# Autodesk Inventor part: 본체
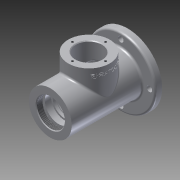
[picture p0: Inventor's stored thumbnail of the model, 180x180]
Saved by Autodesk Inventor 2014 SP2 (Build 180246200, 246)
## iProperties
Created: 2016-08
Part Number: 본체
Material: 알루미늄 6061
Document SubType Name: Modeling
Designer: 달림반
Density: 2.71 g/cm^3
Appearance: 알루미늄 - 평지
Author: 달림반
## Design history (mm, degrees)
sketch "스케치1"
  geometry: L1 (-56, 31)-(59, 31); L2 (59, 31)-(59, 21); L3 (59, 21)-(46.991, 16.711); L4 (45, 13.886)-(45, 12.904); L5 (44.3, 12.5)-(38, 12.5); L6 (37.7, 12.2)-(37.7, 10); L7 (37.7, 10)-(35, 10); L8 (35, 10)-(35, 13.5); L9 (32, 16.5)-(30, 16.5); L10 (30, 16.5)-(30, 17.2); L11 (29.7, 17.5)-(-35, 17.5); L12 (-35, 17.5)-(-35, 20); L13 (-35, 20)-(-44, 20); L14 (-44, 20)-(-44, 24); L15 (-44, 24)-(-47, 24); L16 (-47, 24)-(-47, 20); L17 (-47, 20)-(-56, 20); L18 (-56, 20)-(-56, 31); L19 (0, 0)-(59, 0); L20 (-31.75, 17.5)-(-31.75, 18.5); L21 (-31.75, 18.5)-(-30, 18.5); L22 (-30, 18.5)-(-30, 17.5); L23 (44.3, 12.5)-(45, 12.904); A1 r 0.3 centre (38, 12.2) between (38, 12.5) and (37.7, 12.2); A2 r 0.3 centre (29.7, 17.2) between (30, 17.2) and (29.7, 17.5); A3 r 3 centre (48, 13.886) between (46.991, 16.711) and (45, 13.886); A4 r 3 centre (32, 13.5) between (35, 13.5) and (32, 16.5); 3 further points
  constraints: 47 end point, 12 parallel, 8 point on circle, 8 point on line, 8 tangent, 7 perpendicular, 4 centre point, 1 collinear, 1 equal radius, 1 horizontal, 1 vertical alignment
  dimensions: "d0" = 115 distance between parallel lines of L2 L18; "d1" = 56 distance from line of L19.start L18; "d2" = 62 diameter of L1 L19; "d3" = 42 diameter of L2.end L19; "d4" = 32 diameter of point (45, 16) L19; "d5" = 25 diameter of L5 L19; "d6" = 20 diameter of L7 L19; "d7" = 2.7 distance of L6.end L7.end; "d9" = 33 diameter of L9 L19; "d10" = 40 diameter of L17 L19; "d12" = 48 diameter of L15 L19; "d13" = 12 distance between parallel lines of L14 L18; "d14" = 3 distance of L14.end L15.end; "d15" = 21 distance between parallel lines of L18 L12; "d16" = 40 diameter of L13 L19; "d17" = 35 diameter of L11 L19; "d18" = 1.75 distance of L20.end L21.end; "d19" = 26 distance between parallel lines of L18 L22; "d20" = 37 diameter of L21 L19; "d22" = 14 distance from line of L2 point (45, 16); "d23" = 60 distance between parallel lines of L10 L22; "d24" = 5 distance between parallel lines of L10 L8 (derived); "d25" = 24 distance between parallel lines of L2 L8 (derived); "d26" = 86 distance between parallel lines of L18 L10 (derived); "d27" = 0.3 radius of A1; "d28" = 0.3 radius of A2; "d29" = 30 deg angle of L23 L5; "d30" = 0.7 horizontal distance of L5.start L4.end; "d31" = 7.3 distance between parallel lines of L4 L6; "d33" = 3 radius of A3
revolve "회전1" sketch "스케치1" stored, may be unused: angle "d32" = 90 deg
node "작업 평면1"
sketch "스케치2"
  geometry: C1 r 31 at (0, 0) reference; C2 r 50 at (0, 0); 1 further point
  constraints: 1 centre point, 1 coincident
  dimensions: "d35" = 100 diameter of C2
extrude "돌출1" join sketch "스케치2" distance "d36" = 10; taper "d37" = 0 deg
node "작업 평면2"
sketch "스케치3"
  geometry: C1 r 30 at (0, 0); 1 further point
  constraints: 1 centre point, 1 coincident
  dimensions: "d39" = 60 diameter of C1
extrude "돌출2" join sketch "스케치3" stored distance "d41" = 10; taper "d42" = 0 deg
sketch "스케치4"
  geometry: L1 (-19, 0)-(19, 0); L2 (19, 0)-(19, -26); L3 (19, -26)-(-19, -26); L4 (-19, -26)-(-19, 0); 2 further points
  constraints: 8 end point, 2 parallel, 1 coincident, 1 horizontal, 1 horizontal alignment, 1 midpoint, 1 perpendicular
  dimensions: "d43" = 52 diameter of L3 L1; "d45" = 38 distance between parallel lines of L2 L4
revolve "회전2" sketch "스케치4" stored, may be unused: angle "d44" = 90 deg
sketch "스케치5"
  geometry: C1 r 30 at (0, 0) reference; C2 r 19 at (0, 0)
  constraints: 1 centre point, 1 coincident
  dimensions: "d46" = 38 diameter of C2
extrude "돌출3" cut sketch "스케치5" stored distance "d47" = 10; taper "d48" = 0 deg
hole "구멍1" diameter "d54" = 40.376; stored, may be unused: countersink angle "d58" = 90 deg, drill point angle "d60" = 0 deg; dims "d55" = 6, "d56" = 4, "d57" = 2, "d59" = 9, "d63" = 10, "d64" = 10
chamfer "모따기1" distance "d49" = 1; stored, may be unused: second distance "d50" = 2, angle "d51" = 45 deg
sketch "스케치6" dims "d61" = 83
  geometry: C1 r 31 at (0, 0) reference; C2 r 50 at (0, 0) reference; 2 further points
  constraints: 2 vertical alignment, 1 coincident, 2 other
hole "구멍2" sketch "스케치6" at (0, 41.5) diameter "d62" = 8; stored, may be unused: countersink angle "d68" = 90 deg, drill point angle "d70" = 118 deg; dims "d65" = 6, "d66" = 4, "d67" = 2, "d69" = 9
sketch "스케치7" dims "d74" = 48
  geometry: C1 r 19 at (0, 0) reference; C2 r 30 at (0, 0) reference; 2 further points
  constraints: 2 vertical alignment, 1 coincident, 2 other
hole "구멍3" sketch "스케치7" at (0, 24) diameter "d75" = 3.242; stored, may be unused: countersink angle "d79" = 90 deg, drill point angle "d81" = 118 deg; dims "d76" = 8, "d77" = 4, "d78" = 2, "d80" = 10
node "작업 평면3"
sketch "스케치8"
  geometry: L1 (-56, -31)-(-56, 31) reference; L2 (-30, 49)-(30, 49) reference; 2 further points
  constraints: 1 other
  dimensions: "d86" = 56 distance from line of point (0, 39) L1; "d87" = 10 distance from line of point (0, 39) L2
feature "엠보싱1" sketch "스케치8" dims "d23" = 60, "d88" = 0.5, "d89" = 0
fillet "모깎기1" dims "d90" = 3, "d91" = 2
fillet "모깎기2" dims "d92" = 3
node "솔리드1"
pattern_circular "원형 패턴1" dims angle "d72" = 360 deg
pattern_circular "원형 패턴2" dims angle "d83" = 360 deg
other parameters: "d34" = -13, "d38" = 49, "d85" = 52.75
